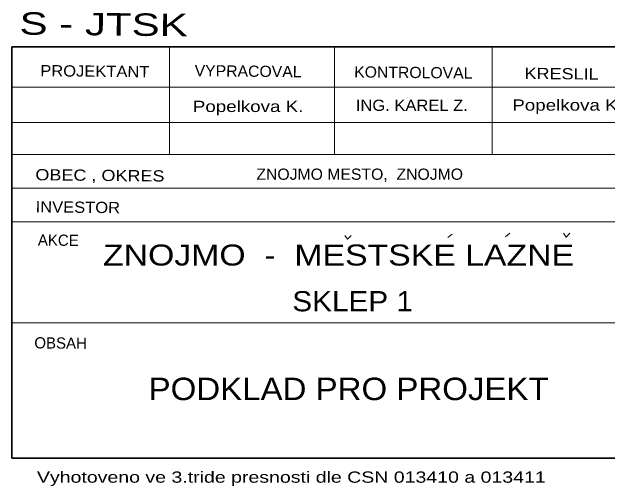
# Model space of a CAD drawing. Extents: x -642923.1 to -642906.9, y -1193255.4 to -1193224.4.
# Drawn here: x -642923.05 to -642912.45, y -1193255.39 to -1193246.94 of the extents above; entities that cross this region are included whole.
import ezdxf
from ezdxf.enums import TextEntityAlignment as Align

# ---------------------------------------------------------------- set-up
doc = ezdxf.new("R2010")
doc.units = 0
doc.header["$LTSCALE"] = 0.08
doc.layers.add('1', color=7, linetype='Continuous', lineweight=13)
doc.layers.add('61', color=7, linetype='Continuous', lineweight=13)

msp = doc.modelspace()

# ---------------------------------------------------------------- linework, layer by layer
at = {"layer": '1'}
for p, q in [((-642915.287, -1193250.964), (-642915.209, -1193250.902)), ((-642914.259, -1193250.95), (-642914.181, -1193250.886))]:
    msp.add_line(p, q, dxfattribs=at)
for points in [[(-642917.119, -1193250.926), (-642917.073, -1193250.996), (-642917.011, -1193250.926)], [(-642913.223, -1193250.886), (-642913.175, -1193250.956), (-642913.113, -1193250.886)]]:
    msp.add_lwpolyline(points, dxfattribs=at)
at = {"layer": '61'}
for p, q in [((-642920.247, -1193247.564), (-642920.247, -1193249.484)), ((-642917.303, -1193247.564), (-642917.303, -1193249.484)), ((-642914.497, -1193247.564), (-642914.497, -1193249.484)), ((-642923.053, -1193248.284), (-642911.691, -1193248.284)), ((-642923.053, -1193248.916), (-642911.691, -1193248.916)), ((-642923.053, -1193249.484), (-642906.861, -1193249.484)), ((-642923.053, -1193250.084), (-642906.861, -1193250.084)), ((-642923.053, -1193250.684), (-642906.861, -1193250.684)), ((-642923.053, -1193252.484), (-642906.861, -1193252.484))]:
    msp.add_line(p, q, dxfattribs=at)
at = {"layer": '61', "lineweight": 35}
msp.add_lwpolyline([(-642923.053, -1193247.564), (-642906.861, -1193247.564), (-642906.861, -1193254.896), (-642923.053, -1193254.896)], close=True, dxfattribs=at)

# ---------------------------------------------------------------- texts
at = {"layer": '1'}
for s, height, width, p in [('Popelkova K.', 0.2, 1.25, (-642918.8445, -1193248.728)), ('ING. KAREL Z.', 0.2, 1.1, (-642915.9275, -1193248.708)), ('Popelkova K.', 0.2, 1.25, (-642913.1525, -1193248.704)), ('ZNOJMO MESTO,  ZNOJMO', 0.2, 1.05, (-642916.8565, -1193249.936)), ('ZNOJMO  -  MESTSKE LAZNE', 0.375, 1.2, (-642917.2335, -1193251.464)), ('SKLEP 1', 0.36, 1.1, (-642916.9825, -1193252.28)), ('PODKLAD PRO PROJEKT', 0.4, 1.1, (-642917.0535, -1193253.862)), ('Vyhotoveno ve 3.tride presnosti dle CSN 013410 a 013411', 0.2, 1.3, (-642918.0745, -1193255.334))]:
    msp.add_text(s, height=height, dxfattribs=dict(at, width=width)).set_placement(p, align=Align.CENTER)
at = {"layer": '61'}
for s, height, width, p in [('S - JTSK', 0.4, 1.4, (-642921.42053, -1193247.36342)), ('PROJEKTANT', 0.2, 1.1, (-642921.57552, -1193248.09982)), ('VYPRACOVAL', 0.2, 1.05, (-642918.84602, -1193248.09974)), ('KONTROLOVAL', 0.2, 1.05, (-642915.90202, -1193248.12275)), ('KRESLIL', 0.2, 1.2, (-642913.26002, -1193248.14469)), ('OBEC , OKRES', 0.2, 1.2, (-642921.48552, -1193249.95581)), ('INVESTOR', 0.2, 1.1, (-642921.87902, -1193250.52376))]:
    msp.add_text(s, height=height, rotation=359.418, dxfattribs=dict(at, width=width)).set_placement(p, align=Align.CENTER)
for s, p in [('AKCE', (-642922.22702, -1193251.1117)), ('OBSAH', (-642922.18602, -1193252.94466))]:
    msp.add_text(s, height=0.2, rotation=359.418, dxfattribs=at).set_placement(p, align=Align.CENTER)

doc.saveas('drawing.dxf')
